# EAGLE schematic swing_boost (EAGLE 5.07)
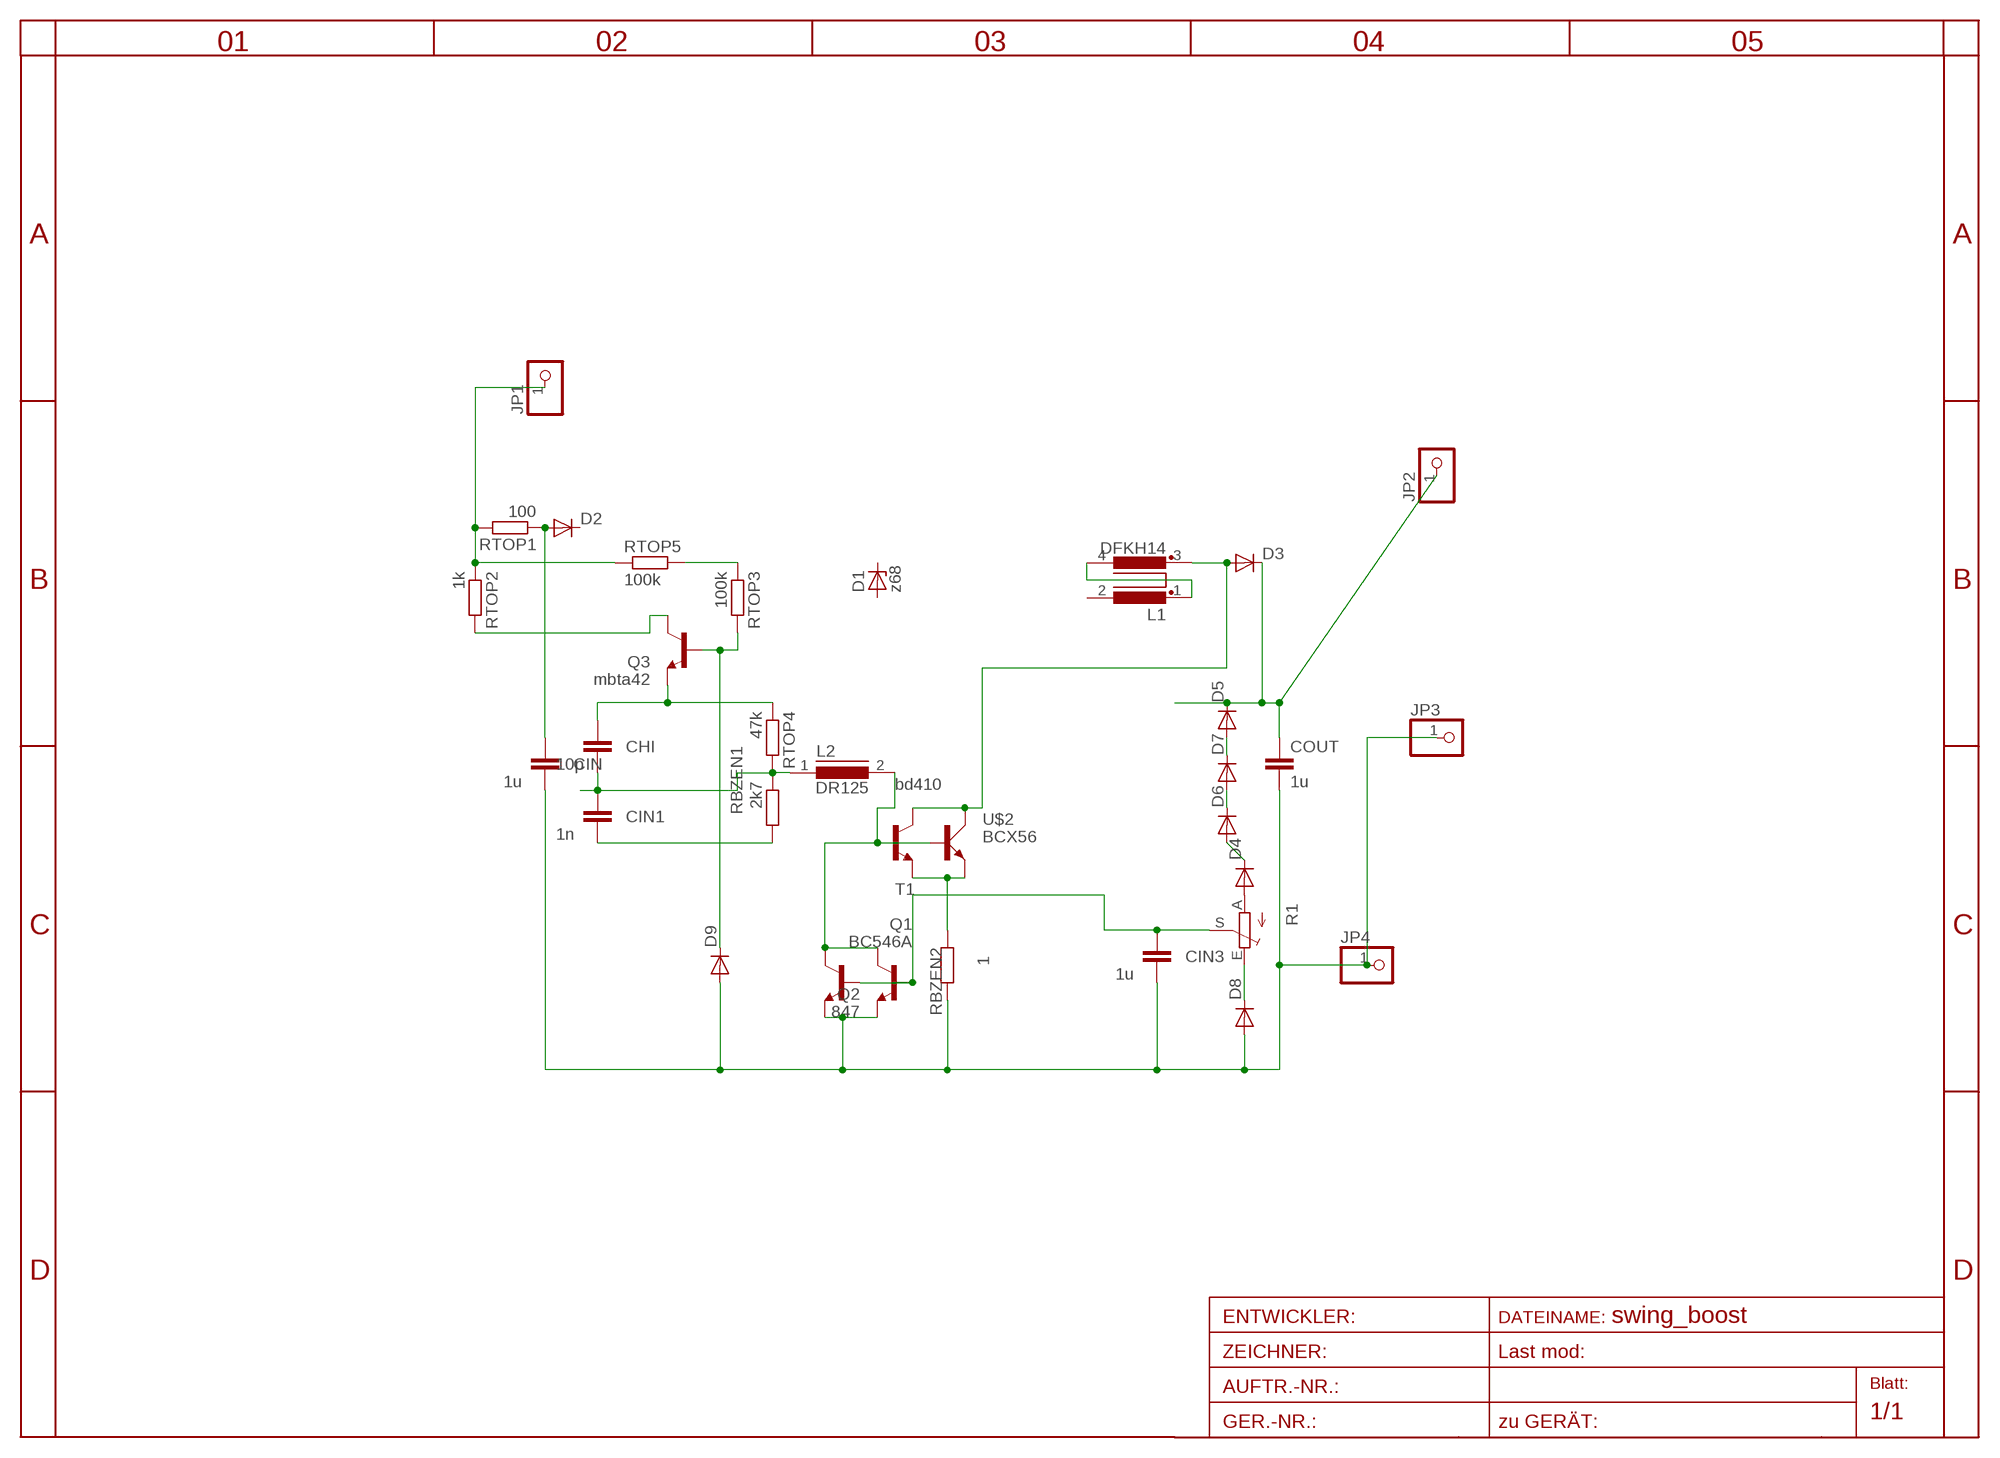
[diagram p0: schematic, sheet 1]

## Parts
CHI  10p  C-EUC0805  [C0805]
CIN  1u  C-EU025-024X044  [C025-024X044]
CIN1  1n  C-EUC0805  [C0805]
CIN3  1u  C-EU025-024X044  [C025-024X044]
COUT  1u  C-EU025_050-055X075  [C025_050-055X075]
D1  z68  ZENER-DIODESOD80C  [SOD80C]
D2  DIODE-SMC  [SMC]
D3  DIODE-SMC  [SMC]
D4  DIODE-MINIMELF  [MINIMELF]
D5  DIODE-MINIMELF  [MINIMELF]
D6  DIODE-MINIMELF  [MINIMELF]
D7  DIODE-MINIMELF  [MINIMELF]
D8  DIODE-MINIMELF  [MINIMELF]
D9  DIODE-MINIMELF  [MINIMELF]
JP1  PINHD-1X11X0.4  [1X01]
JP2  PINHD-1X11X0.4  [1X01]
JP3  PINHD-1X11X0.4  [1X01]
JP4  PINHD-1X11X0.4  [1X01]
L1  DFKH14  DFKH145MM  [ROUND1]
L2  DR125  [DR125]
Q1  BC546A  [TO92-EBC]
Q2  847  BC847ASMD  [SOT23]
Q3  mbta42  BC847ASMD  [SOT23]
R1  TRIM_EU-S64W  [S64W]
RBZEN1  2k7  R-EU_R0805  [R0805]
RBZEN2  1  R-EU_0207/10  [0207/10]
RTOP1  100  R-EU_0207/12  [0207/12]
RTOP2  1k  R-EU_R0805  [R0805]
RTOP3  100k  R-EU_R2010  [R2010]
RTOP4  47k  R-EU_R0805  [R0805]
RTOP5  100k  R-EU_R2010  [R2010]
T1  bd410  -NPN-TO126V  [TO126V]
U$2  BCX56  [SOT223]

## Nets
C: D3.A L1.3 T1.2(C) U$2.2(C)
EE: RBZEN2.1 T1.1(E) U$2.3(E)
GND: CIN3.2 CIN.2 COUT.2 D8.A D9.A JP3.1 JP4.1 Q1.E Q2.2(E) RBZEN2.2
MID: CHI.2 CIN1.1 L2.1 RBZEN1.1 RTOP4.2
N$1: D4.C D6.A
N$2: D6.C D7.A
N$3: L2.2 Q1.C Q2.3(C) T1.3(B) U$2.1(B)
N$4: D5.A D7.C
N$5: CHI.1 Q3.2(E) RTOP4.1
N$7: L1.1 L1.4
N$9: JP1.1 RTOP1.2 RTOP2.1 RTOP5.1
N$10: Q3.3(C) RTOP2.2
N$12: CIN3.1 Q1.B Q2.1(B) R1.S
N$13: CIN1.2 RBZEN1.2
N$14: D9.C Q3.1(B) RTOP3.2
N$15: RTOP3.1 RTOP5.2
N$17: D4.A R1.A
N$18: D8.C R1.E
OUT: COUT.1 D3.C D5.C JP2.1
VPLUS: CIN.1 D2.A RTOP1.1
Unconnected: D1.A D1.C D2.C L1.2

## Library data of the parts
CHI CIN CIN1 CIN3 COUT = rcl:C-EU: CAPACITOR, European symbol
D1 = diode:ZENER-DIODE: Z-Diode
D2-D9 = diode-1:DIODE-: DIODE
JP1-JP4 = pinhead:PINHD-1X1: PIN HEADER
L1 = inductors:DFKH14: FILTER
L2 = inductors:DR125: High Power Density, High Efficiency, Shielded Inductors
Q1 = transistor-npn:BC546*: NPN Transistor
Q2 Q3 = transistor-npn:BC847*: NPN Transistor
R1 = pot-7:TRIM_EU-: POTENTIOMETER
RBZEN1 RBZEN2 RTOP1-RTOP5 = rcl:R-EU_: RESISTOR, European symbol
T1 = transistor:*-NPN-: NPN Transistror BF959 corrected 2008.03.06
U$2 = transistor-power:BCX56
